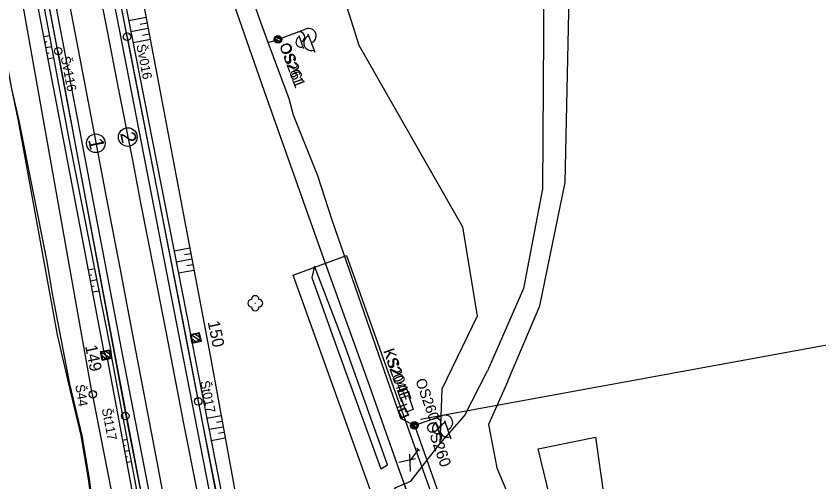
# Model space of a CAD drawing. Extents: x -545967 to -545044, y -1122650 to -1118491.
# Drawn here: x -545744.9 to -545637.8, y -1119158.2 to -1119096.1 of the extents above; entities that cross this region are included whole.
import ezdxf

# ---------------------------------------------------------------- set-up
doc = ezdxf.new("R2010")
doc.units = 0
for name, color, linetype in [('osvětlené plochy-hodnota-obrys', 7, 'Continuous'), ('Vrstva 1', 7, 'Continuous'), ('Vrstva 1 - Koleje', 7, 'Continuous'), ('Vrstva 11 - Trakce', 7, 'Continuous'), ('Vrstva 12', 7, 'Continuous'), ('Vrstva 12 - Trakce zaklady', 7, 'Continuous'), ('Vrstva 25', 7, 'Continuous'), ('Vrstva 25 - silnoproud prvky', 7, 'Continuous'), ('Vrstva 26', 7, 'Continuous'), ('Vrstva 26 - silnoproud', 7, 'Continuous'), ('Vrstva 28 - zabzar', 7, 'Continuous'), ('Vrstva 31', 7, 'Continuous'), ('Vrstva 32', 7, 'Continuous'), ('Vrstva 4', 7, 'Continuous'), ('Vrstva 4 - Teren - stezky - prechody - plochy', 7, 'Continuous'), ('Vrstva 43', 7, 'Continuous'), ('Vrstva 44', 7, 'Continuous'), ('Vrstva 48', 7, 'Continuous'), ('Vrstva 49', 7, 'Continuous'), ('Vrstva 50', 7, 'Continuous'), ('Vrstva 51', 7, 'Continuous'), ('Vrstva 62', 7, 'Continuous'), ('Vrstva 63', 7, 'Continuous')]:
    doc.layers.add(name, color=color, linetype=linetype)

msp = doc.modelspace()

# ---------------------------------------------------------------- linework, layer by layer
at = {"layer": 'osvětlené plochy-hodnota-obrys'}
for points in [[(-545694.33, -1119168.5), (-545707.92, -1119130.61), (-545700.79, -1119127.99)], [(-545700.79, -1119127.99), (-545610.46, -1119381.57), (-545628.87, -1119385.18)]]:
    msp.add_lwpolyline(points, dxfattribs=at)
at = {"layer": 'Vrstva 1'}
msp.add_lwpolyline([(-545730.53, -1119049.44), (-545727.17, -1119060.47), (-545720.47, -1119081.17), (-545711.79, -1119106.08), (-545703.85, -1119128.4), (-545698.02, -1119144.67), (-545693.95, -1119156.14), (-545691.54, -1119162.9), (-545690.15, -1119166.9), (-545689.96, -1119167.44), (-545689.7, -1119168.18), (-545684.74, -1119182.22), (-545679.15, -1119198.02), (-545676.37, -1119205.85), (-545670.92, -1119221.16), (-545664.83, -1119238.34)], dxfattribs=at)
at = {"layer": 'Vrstva 1 - Koleje'}
for points in [[(-545738.2, -1119092.23), (-545736.39, -1119101.71), (-545734.57, -1119111.27), (-545732.86, -1119120.21), (-545731.06, -1119129.63), (-545729.36, -1119138.55), (-545727.68, -1119147.35), (-545726.12, -1119155.52), (-545724.23, -1119165.43), (-545722.4, -1119175.04), (-545720.39, -1119185.57), (-545718.55, -1119195.19), (-545717.29, -1119201.76), (-545715.38, -1119211.67), (-545713.88, -1119219.42), (-545712.26, -1119227.81), (-545710.34, -1119237.73), (-545708.56, -1119246.89)], [(-545734, -1119091.55), (-545732.95, -1119096.94), (-545731.2, -1119105.88), (-545729.37, -1119115.29), (-545728.27, -1119120.97), (-545726.47, -1119130.18), (-545724.6, -1119139.73), (-545722.57, -1119150.15), (-545720.7, -1119159.75), (-545718.64, -1119170.34), (-545716.6, -1119180.78), (-545714.64, -1119190.84), (-545712.79, -1119200.31), (-545711.64, -1119206.25), (-545709.73, -1119216.01), (-545707.22, -1119228.93), (-545705.34, -1119238.54), (-545703.89, -1119245.98)]]:
    msp.add_lwpolyline(points, dxfattribs=at)
for centre in [(-545729.98, -1119112.2), (-545734.24, -1119113.03)]:
    msp.add_circle(centre, 1.24, dxfattribs=at)
at = {"layer": 'Vrstva 11 - Trakce'}
for p, q in [((-545721.5, -1119138.56), (-545720.32, -1119139.34)), ((-545721.4, -1119139.08), (-545720.84, -1119139.45)), ((-545720.98, -1119138.46), (-545720.43, -1119138.82)), ((-545733.49, -1119140.86), (-545732.31, -1119141.64)), ((-545733.39, -1119141.38), (-545732.83, -1119141.75)), ((-545732.97, -1119140.76), (-545732.42, -1119141.12))]:
    msp.add_line(p, q, dxfattribs=at)
for points in [[(-545720.53, -1119138.36), (-545720.32, -1119139.34), (-545721.3, -1119139.54), (-545721.51, -1119138.56)], [(-545732.51, -1119140.66), (-545732.31, -1119141.64), (-545733.29, -1119141.84), (-545733.49, -1119140.86)]]:
    msp.add_lwpolyline(points, close=True, dxfattribs=at)
at = {"layer": 'Vrstva 12'}
msp.add_line((-545693.45, -1119149.67), (-545693.87, -1119148.71), dxfattribs=at)
for points in [[(-545693.83, -1119148.76), (-545693.87, -1119148.71), (-545692.98, -1119148.32), (-545692.97, -1119148.36)], [(-545692.98, -1119148.32), (-545692.54, -1119149.26), (-545692.57, -1119149.23)], [(-545692.54, -1119149.26), (-545693.45, -1119149.67), (-545693.43, -1119149.6)]]:
    msp.add_lwpolyline(points, dxfattribs=at)
msp.add_lwpolyline([(-545693.83, -1119148.76), (-545692.97, -1119148.36), (-545692.57, -1119149.23), (-545693.43, -1119149.6)], close=True, dxfattribs=at)
at = {"layer": 'Vrstva 12 - Trakce zaklady'}
for p, q in [((-545721.66, -1119138.55), (-545720.39, -1119138.29)), ((-545721.42, -1119139.68), (-545720.16, -1119139.43)), ((-545733.61, -1119140.8), (-545732.36, -1119140.59)), ((-545733.38, -1119141.93), (-545732.13, -1119141.7))]:
    msp.add_line(p, q, dxfattribs=at)
for points in [[(-545721.66, -1119138.55), (-545721.42, -1119139.68), (-545720.16, -1119139.43), (-545720.39, -1119138.29), (-545721.66, -1119138.55)], [(-545721.66, -1119138.55), (-545721.66, -1119138.55), (-545721.42, -1119139.68), (-545721.42, -1119139.68)], [(-545732.36, -1119140.59), (-545732.13, -1119141.7), (-545733.38, -1119141.93), (-545733.61, -1119140.8), (-545732.36, -1119140.59)], [(-545733.61, -1119140.8), (-545733.61, -1119140.8), (-545733.38, -1119141.93), (-545733.38, -1119141.93)], [(-545732.36, -1119140.59), (-545732.36, -1119140.59), (-545732.13, -1119141.7), (-545732.13, -1119141.7)]]:
    msp.add_lwpolyline(points, dxfattribs=at)
at = {"layer": 'Vrstva 25'}
for p, q in [((-545709.48, -1119099.01), (-545706.2, -1119097.78)), ((-545705.96, -1119098.44), (-545705.05, -1119100.88)), ((-545710.44, -1119099.11), (-545709.57, -1119099.51)), ((-545710.26, -1119098.79), (-545709.45, -1119099.15)), ((-545691.28, -1119150.48), (-545687.97, -1119149.32)), ((-545687.74, -1119149.98), (-545686.89, -1119152.44)), ((-545692.24, -1119150.56), (-545691.38, -1119150.97)), ((-545692.05, -1119150.24), (-545691.25, -1119150.62))]:
    msp.add_line(p, q, dxfattribs=at)
msp.add_lwpolyline([(-545693.5, -1119146.97), (-545692.55, -1119146.64), (-545691.9, -1119148.53), (-545692.84, -1119148.86), (-545693.5, -1119146.97)], dxfattribs=at)
for centre in [(-545709.95, -1119099.18), (-545709.95, -1119099.18), (-545691.75, -1119150.64), (-545691.75, -1119150.64)]:
    msp.add_circle(centre, 0.5, dxfattribs=at)
for centre, start, end in [((-545705.52, -1119099.66), 109.779, 291.1841), ((-545705.85, -1119098.72), 290.4816, 110.4816), ((-545687.64, -1119150.26), 289.2609, 109.2609), ((-545687.33, -1119151.21), 108.5584, 289.9635)]:
    msp.add_arc(centre, 1, start, end, dxfattribs=at)
at = {"layer": 'Vrstva 25 - silnoproud prvky'}
for p, q in [((-545709.62, -1119099.06), (-545707.33, -1119098.2)), ((-545707.16, -1119098.66), (-545706.52, -1119100.37)), ((-545710.3, -1119099.13), (-545709.69, -1119099.41)), ((-545710.16, -1119098.91), (-545709.6, -1119099.16)), ((-545691.42, -1119150.52), (-545689.11, -1119149.72)), ((-545692.09, -1119150.58), (-545691.49, -1119150.87)), ((-545691.96, -1119150.36), (-545691.4, -1119150.63)), ((-545688.95, -1119150.18), (-545688.34, -1119151.9))]:
    msp.add_line(p, q, dxfattribs=at)
msp.add_lwpolyline([(-545693.5, -1119146.97), (-545692.55, -1119146.64), (-545691.9, -1119148.53), (-545692.84, -1119148.86), (-545693.5, -1119146.97)], dxfattribs=at)
for centre in [(-545709.95, -1119099.18), (-545691.75, -1119150.64)]:
    msp.add_circle(centre, 0.35, dxfattribs=at)
for centre, start, end in [((-545707.08, -1119098.86), 290.4816, 110.4816), ((-545706.85, -1119099.52), 109.779, 291.1841), ((-545688.88, -1119150.38), 289.2609, 109.2609), ((-545688.65, -1119151.04), 108.5584, 289.9635)]:
    msp.add_arc(centre, 0.7, start, end, dxfattribs=at)
at = {"layer": 'Vrstva 26'}
for points in [[(-545691.75, -1119150.64), (-545693.54, -1119149.74), (-545694.06, -1119148.25), (-545694.58, -1119146.76), (-545702.72, -1119123.3), (-545704.61, -1119117.38), (-545707.88, -1119109.27), (-545708.44, -1119107.12), (-545711.24, -1119099.61), (-545712.5, -1119096.16), (-545714.8, -1119089.4)], [(-545711.24, -1119099.61), (-545709.95, -1119099.18)], [(-545694.06, -1119148.25), (-545692.7, -1119147.75)], [(-545660.17, -1119237.42), (-545663.33, -1119228.72), (-545664.43, -1119225.85), (-545667.92, -1119216.78), (-545673.57, -1119200.8), (-545677.95, -1119188.6), (-545682.48, -1119176.49), (-545687.39, -1119162.87), (-545691.44, -1119151.43), (-545691.75, -1119150.64)], [(-545687.39, -1119162.87), (-545691.44, -1119151.43)]]:
    msp.add_lwpolyline(points, dxfattribs=at)
at = {"layer": 'Vrstva 26 - silnoproud'}
for points in [[(-545748.72, -1119088.79), (-545745.5, -1119105.78), (-545744.59, -1119110.02), (-545739.38, -1119138.56), (-545737.89, -1119145.12), (-545736.24, -1119151.98), (-545735.25, -1119157.79), (-545734.75, -1119161.66), (-545734.7, -1119163.85), (-545735.24, -1119167.68), (-545737.05, -1119172.51), (-545737.3, -1119173.49), (-545737.95, -1119181.49), (-545735.15, -1119195.91), (-545734.32, -1119200.74), (-545732.62, -1119201.11)], [(-545691.75, -1119150.64), (-545693.54, -1119149.74), (-545694.06, -1119148.25), (-545694.58, -1119146.76), (-545702.72, -1119123.3), (-545704.61, -1119117.38), (-545707.88, -1119109.27), (-545708.44, -1119107.12), (-545711.24, -1119099.61), (-545712.5, -1119096.16), (-545714.8, -1119089.4)], [(-545711.24, -1119099.61), (-545709.95, -1119099.18)], [(-545694.06, -1119148.25), (-545692.7, -1119147.75)], [(-545660.17, -1119237.42), (-545663.33, -1119228.72), (-545664.43, -1119225.85), (-545667.92, -1119216.78), (-545673.57, -1119200.8), (-545677.95, -1119188.6), (-545682.48, -1119176.49), (-545687.39, -1119162.87), (-545691.44, -1119151.43), (-545691.75, -1119150.64)], [(-545687.39, -1119162.87), (-545691.44, -1119151.43)]]:
    msp.add_lwpolyline(points, dxfattribs=at)
at = {"layer": 'Vrstva 28 - zabzar'}
msp.add_lwpolyline([(-545724.37, -1119249.99), (-545724.69, -1119248.61), (-545727.23, -1119235.34), (-545728.99, -1119226.34), (-545732.03, -1119209.67), (-545734.16, -1119200.74), (-545735.82, -1119191.07), (-545737.79, -1119181.49), (-545737.14, -1119173.49), (-545736.89, -1119172.51), (-545735.08, -1119167.68), (-545734.54, -1119163.85), (-545734.59, -1119161.66), (-545735.09, -1119157.79), (-545736.08, -1119151.98), (-545737.73, -1119145.12), (-545739.97, -1119133.32), (-545740.77, -1119128.56), (-545744.45, -1119110.05), (-545745.46, -1119105.77), (-545746.9, -1119097.66), (-545750.31, -1119079.79)], dxfattribs=at)
at = {"layer": 'Vrstva 31'}
msp.add_lwpolyline([(-545724.37, -1119249.99), (-545724.69, -1119248.61), (-545727.23, -1119235.34), (-545728.99, -1119226.34), (-545732.03, -1119209.67), (-545734.16, -1119200.74), (-545735.82, -1119191.07), (-545737.79, -1119181.49), (-545737.14, -1119173.49), (-545736.89, -1119172.51), (-545735.08, -1119167.68), (-545734.54, -1119163.85), (-545734.59, -1119161.66), (-545735.09, -1119157.79), (-545736.08, -1119151.98), (-545737.73, -1119145.12), (-545739.97, -1119133.32), (-545740.77, -1119128.56), (-545744.45, -1119110.05), (-545745.46, -1119105.77), (-545746.9, -1119097.66), (-545750.31, -1119079.79)], dxfattribs=at)
at = {"layer": 'Vrstva 32'}
msp.add_lwpolyline([(-545724.37, -1119249.99), (-545724.69, -1119248.61), (-545727.23, -1119235.34), (-545728.99, -1119226.34), (-545732.03, -1119209.67), (-545734.16, -1119200.74), (-545735.66, -1119191.53), (-545735.82, -1119191.07), (-545737.79, -1119181.49), (-545737.14, -1119173.49), (-545736.89, -1119172.51), (-545735.08, -1119167.68), (-545734.54, -1119163.85), (-545734.59, -1119161.66), (-545735.09, -1119157.79), (-545736.08, -1119151.98), (-545737.73, -1119145.12), (-545739.97, -1119133.32), (-545740.77, -1119128.56), (-545744.45, -1119110.05), (-545745.46, -1119105.77), (-545746.9, -1119097.66), (-545750.31, -1119079.79)], dxfattribs=at)
at = {"layer": 'Vrstva 4'}
for p, q in [((-545691.25, -1119153.88), (-545692.32, -1119155.26)), ((-545691.05, -1119154.03), (-545691.44, -1119153.72)), ((-545691.58, -1119155.11), (-545693.84, -1119155.57)), ((-545692.26, -1119156.8), (-545692.36, -1119154.49)), ((-545693.95, -1119156.14), (-545691.54, -1119162.9))]:
    msp.add_line(p, q, dxfattribs=at)
msp.add_lwpolyline([(-545696.24, -1119156.44), (-545695.33, -1119155.91), (-545700.98, -1119140.07), (-545705.06, -1119129.4), (-545705.44, -1119130.93), (-545702.05, -1119140.38)], close=True, dxfattribs=at)
at = {"layer": 'Vrstva 4 - Teren - stezky - prechody - plochy'}
for points in [[(-545842.99, -1118523.92), (-545841.7, -1118530.4), (-545836.85, -1118554.45), (-545831.05, -1118584.6), (-545819.35, -1118645.26), (-545811.23, -1118686.91), (-545799.53, -1118746.65), (-545788.53, -1118802.77), (-545777.85, -1118857.7), (-545765.83, -1118919.34), (-545755.98, -1118970.18), (-545745.51, -1119023.12), (-545734.81, -1119078.88), (-545723.15, -1119138.68), (-545711.33, -1119199.26), (-545707.51, -1119218.93), (-545706.35, -1119218.8)], [(-545711.32, -1119247.44), (-545711.9, -1119243.96), (-545720.22, -1119201.67), (-545721.28, -1119195.76), (-545731.55, -1119141.71), (-545737.08, -1119112.42), (-545743.44, -1119079.1), (-545754.28, -1119022.01), (-545764.13, -1118971.24), (-545774.7, -1118917.12), (-545786.1, -1118858.18), (-545797, -1118803.41), (-545807.66, -1118749.42), (-545819.91, -1118686.43), (-545828.53, -1118641.36), (-545850.15, -1118530.53), (-545851.16, -1118525.52)], [(-545710.22, -1119247.22), (-545719, -1119201.39), (-545730.62, -1119141.39), (-545736.21, -1119112.21), (-545742.56, -1119078.93), (-545753.41, -1119021.81), (-545763.36, -1118970.94), (-545773.92, -1118916.71), (-545785.33, -1118858.19), (-545796.21, -1118802.91), (-545806.84, -1118748.63), (-545819.21, -1118686.19), (-545827.82, -1118641.01), (-545849.34, -1118530.25), (-545850.41, -1118525.37)], [(-545787.71, -1118802.92), (-545777.14, -1118857.58), (-545765.12, -1118918.89), (-545755.12, -1118970.55), (-545744.47, -1119024.93), (-545734.12, -1119078.34), (-545722.33, -1119138.41), (-545711.22, -1119196.15), (-545707.54, -1119214.27), (-545707.41, -1119215.2), (-545706.35, -1119218.8)]]:
    msp.add_lwpolyline(points, dxfattribs=at)
at = {"layer": 'Vrstva 43'}
for centre in [(-545730.07, -1119098.82), (-545739.26, -1119100.75), (-545734.64, -1119146.5), (-545720.58, -1119147.45), (-545730.31, -1119149.39)]:
    msp.add_circle(centre, 0.5, dxfattribs=at)
at = {"layer": 'Vrstva 44'}
for points in [[(-545730.08, -1119098.83), (-545737.37, -1119060.45), (-545745.2, -1119020.61), (-545752.53, -1118984.22)], [(-545739.31, -1119100.74), (-545746.71, -1119061.8), (-545754.21, -1119022.59), (-545761.47, -1118985.92), (-545761.57, -1118985.76)], [(-545744.06, -1119094.17), (-545734.82, -1119146.14), (-545734.75, -1119146.55), (-545734.66, -1119146.89), (-545724.72, -1119197.31), (-545724.66, -1119197.69), (-545724.66, -1119198.01), (-545716.42, -1119241.32), (-545716.38, -1119241.69), (-545716.36, -1119242.06), (-545715.18, -1119248.19)], [(-545730.08, -1119098.83), (-545720.6, -1119147.44), (-545711.11, -1119195.25), (-545720.82, -1119196.36), (-545721.01, -1119196.41)], [(-545739.31, -1119100.74), (-545730.26, -1119149.37), (-545721.1, -1119196.21), (-545721.01, -1119196.41)]]:
    msp.add_lwpolyline(points, dxfattribs=at)
at = {"layer": 'Vrstva 48'}
for p, q in [((-545727.52, -1119096.26), (-545729.84, -1119096.7)), ((-545727.38, -1119097), (-545728.31, -1119097.18)), ((-545741.19, -1119098.8), (-545740.39, -1119098.65)), ((-545727.24, -1119097.74), (-545729.55, -1119098.17)), ((-545727.1, -1119098.47), (-545728.02, -1119098.65)), ((-545741.05, -1119099.53), (-545740.73, -1119099.47)), ((-545726.96, -1119099.21), (-545729.26, -1119099.65)), ((-545740.91, -1119100.27), (-545740.11, -1119100.12)), ((-545740.77, -1119101.01), (-545740.45, -1119100.95)), ((-545740.63, -1119101.75), (-545739.84, -1119101.59)), ((-545721.71, -1119127.02), (-545723.81, -1119127.42)), ((-545721.43, -1119128.49), (-545723.52, -1119128.89)), ((-545721.57, -1119127.76), (-545722.4, -1119127.92)), ((-545735.25, -1119129.9), (-545734.39, -1119129.73)), ((-545721.29, -1119129.23), (-545722.12, -1119129.39)), ((-545735.11, -1119130.63), (-545734.76, -1119130.57)), ((-545721.15, -1119129.97), (-545723.23, -1119130.36)), ((-545734.97, -1119131.37), (-545734.1, -1119131.2)), ((-545734.83, -1119132.11), (-545734.48, -1119132.04)), ((-545734.69, -1119132.84), (-545733.81, -1119132.68)), ((-545717.53, -1119149.39), (-545719.43, -1119149.74)), ((-545717.39, -1119150.13), (-545718.15, -1119150.27)), ((-545717.26, -1119150.86), (-545719.14, -1119151.21)), ((-545717.12, -1119151.6), (-545717.87, -1119151.74)), ((-545730.64, -1119152.61), (-545730.07, -1119152.5)), ((-545730.5, -1119153.34), (-545730.27, -1119153.3)), ((-545716.99, -1119152.34), (-545718.86, -1119152.68)), ((-545730.37, -1119154.08), (-545729.79, -1119153.97)), ((-545730.23, -1119154.82), (-545730, -1119154.78)), ((-545730.09, -1119155.56), (-545729.51, -1119155.45))]:
    msp.add_line(p, q, dxfattribs=at)
at = {"layer": 'Vrstva 49'}
for points in [[(-545839.31, -1118523.2), (-545838.1, -1118529.58), (-545837.4, -1118533.49), (-545832.71, -1118555.7), (-545825.14, -1118594.38), (-545814.25, -1118651.35), (-545808.03, -1118685.15), (-545795.16, -1118750.19), (-545783.94, -1118809.71), (-545774.85, -1118856.95), (-545763.42, -1118915.04), (-545752.93, -1118968.66), (-545741.71, -1119025.95), (-545730.22, -1119081.99), (-545719, -1119141.33), (-545708.86, -1119196.83), (-545704.64, -1119214.15)], [(-545795.7, -1118699.53), (-545788.23, -1118737.74), (-545783.17, -1118774.2), (-545777.68, -1118791.96), (-545766.25, -1118834.9), (-545762.23, -1118863.52), (-545750.54, -1118910.15), (-545748.76, -1118933.68), (-545738.23, -1118978.24), (-545734.45, -1118993.37), (-545726.8, -1119029.27), (-545708.68, -1119069.73), (-545699.17, -1119099.96), (-545685.31, -1119124.18), (-545683.36, -1119136.06), (-545688.07, -1119145.8), (-545688.34, -1119153.09)], [(-545785.57, -1118809.02), (-545776.46, -1118857.74), (-545776.22, -1118859.03), (-545764.99, -1118916.44), (-545764.66, -1118917.89), (-545754.45, -1118970.66), (-545754.17, -1118971.99), (-545744.32, -1119022.63), (-545744.06, -1119023.95), (-545733.43, -1119078.43), (-545721.62, -1119138.52), (-545721.39, -1119139.74), (-545710.15, -1119197.12), (-545709.97, -1119198.73), (-545706.79, -1119214.14), (-545707.41, -1119215.2), (-545706.35, -1119218.8), (-545705.86, -1119218.83), (-545705.11, -1119218.76), (-545703.5, -1119218.63), (-545703.07, -1119219.32), (-545701.68, -1119223.93)], [(-545712.35, -1119247.64), (-545712.92, -1119244.63), (-545721.55, -1119201.11), (-545732.64, -1119141.94), (-545733.19, -1119140.67), (-545738.44, -1119113.17), (-545744.26, -1119082.79), (-545744.78, -1119080.35), (-545754.15, -1119031.65), (-545755.21, -1119026.18), (-545765.27, -1118974.15), (-545765.5, -1118972.76), (-545775.82, -1118920.18), (-545776.08, -1118918.77), (-545787.25, -1118861.28), (-545787.56, -1118859.78), (-545796.82, -1118811)], [(-545711.32, -1119247.44), (-545711.9, -1119243.96), (-545720.22, -1119201.67), (-545721.28, -1119195.76), (-545721.94, -1119195.52), (-545732.08, -1119141.82), (-545732.26, -1119140.52), (-545737.74, -1119112.72), (-545743.31, -1119083.13), (-545744.04, -1119079.56), (-545753.26, -1119031.33), (-545754, -1119028.94), (-545754.15, -1119025.93), (-545754.49, -1119024.32), (-545754.82, -1119024.3), (-545764.54, -1118973.99), (-545764.79, -1118972.58), (-545775.11, -1118920.03), (-545775.4, -1118918.54), (-545786.58, -1118861.09), (-545786.92, -1118859.55), (-545796.32, -1118810.9)], [(-545675.23, -1119153.75), (-545667.59, -1119152.22), (-545664.68, -1119172.67), (-545661.17, -1119193.1)], [(-545651.03, -1119235.64), (-545664.98, -1119193.66), (-545670.4, -1119173.74), (-545675.23, -1119153.75)]]:
    msp.add_lwpolyline(points, dxfattribs=at)
at = {"layer": 'Vrstva 50'}
msp.add_line((-545713.01, -1119134.35), (-545712.94, -1119134.35), dxfattribs=at)
for centre, start, end in [((-545713.48, -1119134.35), 90, 270), ((-545712.98, -1119133.85), 0, 180), ((-545712.48, -1119134.35), 270, 90), ((-545712.98, -1119134.85), 180, 0)]:
    msp.add_arc(centre, 0.5, start, end, dxfattribs=at)
at = {"layer": 'Vrstva 51'}
for points in [[(-545699.47, -1119201.94), (-545698.55, -1119164.45), (-545694.23, -1119158.92), (-545692.24, -1119158.08), (-545688.34, -1119153.09), (-545685.06, -1119149.37), (-545681.98, -1119143.38)], [(-545679.27, -1119144.73), (-545681.86, -1119150.52), (-545680.76, -1119156.32), (-545673.05, -1119174.67)]]:
    msp.add_lwpolyline(points, dxfattribs=at)
at = {"layer": 'Vrstva 62'}
for points in [[(-545639.39, -1118963.7), (-545653.24, -1118996.91), (-545663.11, -1119028.92), (-545672.45, -1119072.2), (-545674.49, -1119091.53), (-545674.65, -1119119.09), (-545677.2, -1119132.37), (-545681.98, -1119143.38)], [(-545679.27, -1119144.73), (-545675.02, -1119134.71), (-545671.64, -1119118.26), (-545671.1, -1119093.47), (-545669.2, -1119070.6), (-545660.95, -1119031.56), (-545650.15, -1118998.91), (-545637.81, -1118968.55)]]:
    msp.add_lwpolyline(points, dxfattribs=at)
at = {"layer": 'Vrstva 63'}
msp.add_line((-545626.71, -1119138.12), (-545690.95, -1119149.85), dxfattribs=at)

# ---------------------------------------------------------------- texts
at = {"layer": 'Vrstva 1 - Koleje'}
for s, p in [('2', (-545731, -1119111.7)), ('1', (-545735.26, -1119112.54))]:
    msp.add_text(s, height=2, rotation=281.0347, dxfattribs=at).set_placement(p)
at = {"layer": 'Vrstva 11 - Trakce'}
for s, rotation, p in [('150', 281.6793, (-545719.33, -1119136.85)), ('149', 281.5376, (-545735.68, -1119140.07))]:
    msp.add_text(s, height=1.6, rotation=rotation, dxfattribs=at).set_placement(p)
at = {"layer": 'Vrstva 25'}
for s, rotation, p in [('OS261', 290.4816, (-545709.8, -1119099.95)), ('KS204E', 289.2044, (-545695.92, -1119140.7)), ('OS260', 289.2609, (-545690.26, -1119150.44))]:
    msp.add_text(s, height=1.5, rotation=rotation, dxfattribs=at).set_placement(p)
at = {"layer": 'Vrstva 25 - silnoproud prvky'}
for s, rotation, p in [('OS261', 290.4816, (-545709.8, -1119099.95)), ('KS204E', 289.2044, (-545695.92, -1119140.7)), ('OS260', 289.2609, (-545691.63, -1119144.65))]:
    msp.add_text(s, height=1.4, rotation=rotation, dxfattribs=at).set_placement(p)
at = {"layer": 'Vrstva 43'}
for s, rotation, p in [('Šv016', 280.9998, (-545728.84, -1119099.94)), ('Šv116', 280.9998, (-545738.92, -1119101.55)), ('Št017', 280.9998, (-545720.32, -1119144.79)), ('Š44', 279.317, (-545736.99, -1119145.28)), ('Št117', 280.9998, (-545733.46, -1119148.45))]:
    msp.add_text(s, height=1.25, rotation=rotation, dxfattribs=at).set_placement(p)

doc.saveas('drawing.dxf')
